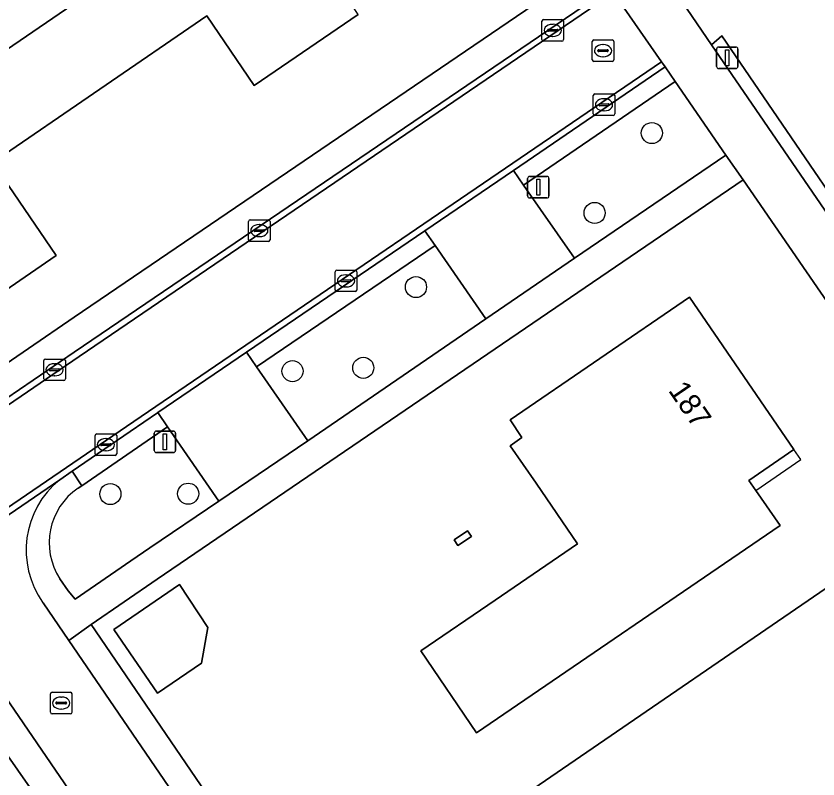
# Model space of a CAD drawing. Extents: x 155275 to 156265, y 382654 to 383635.
# Drawn here: x 155691.51 to 155728.69, y 383451.27 to 383486.64 of the extents above; entities that cross this region are included whole.
import ezdxf

# ---------------------------------------------------------------- set-up
doc = ezdxf.new("R2010")
doc.units = 0
for name, color, linetype in [('IMGEO_Boom', 7, 'Continuous'), ('IMGEO_Erf', 7, 'Continuous'), ('IMGEO_Groenvoorziening', 7, 'Continuous'), ('IMGEO_Haag', 7, 'Continuous'), ('IMGEO_Kolk', 7, 'Continuous'), ('IMGEO_Lichtmast', 7, 'Continuous'), ('IMGEO_Pand', 7, 'Continuous'), ('IMGEO_Pand_nummerreeks', 7, 'Continuous'), ('IMGEO_Pand_overbouw', 7, 'Continuous'), ('IMGEO_Parkeervlak_open', 7, 'Continuous'), ('IMGEO_Rijbaan_lokaal_open', 7, 'Continuous'), ('IMGEO_Rioolput', 7, 'Continuous'), ('IMGEO_Voetpad_open', 7, 'Continuous')]:
    doc.layers.add(name, color=color, linetype=linetype)

msp = doc.modelspace()

# ---------------------------------------------------------------- linework, layer by layer
at = {"layer": 'IMGEO_Boom'}
for centre in [(155720.99, 383481.218), (155718.335, 383477.515), (155710.055, 383474.077), (155707.611, 383470.332), (155704.33, 383470.178), (155695.889, 383464.48), (155699.492, 383464.498)]:
    msp.add_circle(centre, 0.489, dxfattribs=at)
at = {"layer": 'IMGEO_Erf'}
for points in [[(155689.952, 383469.783), (155694.204, 383472.684), (155718.29, 383489.069), (155700.65, 383514.84)], [(155707.38, 383486.712), (155702.557, 383483.422), (155700.359, 383486.653), (155690.422, 383479.861), (155693.377, 383475.537), (155688.352, 383472.093), (155683.164, 383479.665), (155687.692, 383482.78), (155695.373, 383488.031)]]:
    msp.add_lwpolyline(points, dxfattribs=at)
for points in [[(155734.512, 383465.559), (155725.215, 383479.049), (155698.054, 383460.537), (155694.998, 383458.429), (155719.873, 383421.949), (155720.07, 383422.058), (155723.062, 383417.667), (155735.929, 383398.789), (155735.874, 383398.763), (155746.045, 383383.83), (155750.929, 383387.164), (155776.093, 383404.417), (155774.449, 383406.803)], [(155712.867, 383453.41), (155710.28, 383457.206), (155713.724, 383459.565), (155717.539, 383462.177), (155715.621, 383464.979), (155714.427, 383466.723), (155714.968, 383467.095), (155714.413, 383467.914), (155722.736, 383473.61), (155727.576, 383466.544), (155725.489, 383465.114), (155725.811, 383464.647), (155726.93, 383463.025)], [(155711.824, 383462.355), (155712.45, 383462.77), (155712.622, 383462.512), (155711.996, 383462.096)], [(155717.664, 383447.195), (155717.921, 383446.826), (155717.566, 383446.593), (155710.254, 383441.58), (155707.639, 383445.383), (155714.926, 383450.427), (155730.979, 383461.428), (155735.677, 383454.594), (155724.14, 383446.672), (155721.829, 383450.056)], [(155699.086, 383460.279), (155700.405, 383458.293), (155700.109, 383456.632), (155698.071, 383455.241), (155696.048, 383458.205)], [(155689.573, 383454.56), (155686.888, 383452.74), (155667.515, 383439.536), (155668.209, 383438.49), (155691.786, 383403.993), (155718.509, 383364.995), (155740.511, 383380.044), (155700.458, 383438.718), (155700.636, 383438.742)]]:
    msp.add_lwpolyline(points, close=True, dxfattribs=at)
at = {"layer": 'IMGEO_Groenvoorziening'}
for points in [[(155720.532, 383490.035), (155723.759, 383485.312), (155724.227, 383485.725), (155777.645, 383407.499), (155785.035, 383418.096), (155785.37, 383418.576), (155786.992, 383420.901), (155789.946, 383428.782), (155786.989, 383433.092)], [(155693.549, 383460.553), (155693.935, 383459.991), (155694.252, 383459.599), (155696.833, 383461.38), (155697.716, 383461.989), (155700.919, 383464.146), (155698.538, 383467.603)], [(155698.538, 383467.603), (155694.561, 383464.865), (155694.394, 383464.75)]]:
    msp.add_lwpolyline(points, dxfattribs=at)
for points in [[(155724.227, 383485.725), (155723.759, 383485.312), (155746.216, 383452.521), (155760.092, 383432.137), (155777.308, 383407.016), (155777.645, 383407.499)], [(155722.073, 383483.608), (155715.031, 383478.804), (155717.396, 383475.423), (155724.422, 383480.2)], [(155705.034, 383466.948), (155713.291, 383472.603), (155710.944, 383476.009), (155702.66, 383470.375)]]:
    msp.add_lwpolyline(points, close=True, dxfattribs=at)
msp.add_arc((155696.094, 383462.224), 3.045, 123.9409, 213.2923, dxfattribs=at)
at = {"layer": 'IMGEO_Haag'}
msp.add_lwpolyline([(155724.227, 383485.725), (155723.759, 383485.312), (155746.216, 383452.521), (155760.092, 383432.137), (155777.308, 383407.016), (155777.645, 383407.499)], close=True, dxfattribs=at)
at = {"layer": 'IMGEO_Kolk'}
for p, q in [((155715.97, 383486.48), (155716.822, 383486.48)), ((155715.895, 383485.554), (155715.895, 383486.406)), ((155716.383, 383486.26), (155716.408, 383486.26)), ((155716.896, 383486.406), (155716.896, 383485.554)), ((155716.154, 383485.974), (155716.154, 383485.986)), ((155716.592, 383485.937), (155716.194, 383485.937)), ((155716.197, 383486.023), (155716.595, 383486.023)), ((155716.406, 383485.7), (155716.381, 383485.7)), ((155716.638, 383485.986), (155716.638, 383485.974)), ((155716.822, 383485.48), (155715.97, 383485.48)), ((155718.27, 383482.104), (155718.27, 383482.956)), ((155718.345, 383483.03), (155719.197, 383483.03)), ((155718.758, 383482.81), (155718.783, 383482.81)), ((155719.271, 383482.956), (155719.271, 383482.104)), ((155718.529, 383482.524), (155718.529, 383482.536)), ((155718.967, 383482.487), (155718.569, 383482.487)), ((155718.572, 383482.573), (155718.97, 383482.573)), ((155719.013, 383482.536), (155719.013, 383482.524)), ((155719.197, 383482.03), (155718.345, 383482.03)), ((155718.781, 383482.25), (155718.756, 383482.25)), ((155702.367, 383477.196), (155703.219, 383477.196)), ((155702.292, 383476.27), (155702.292, 383477.122)), ((155702.78, 383476.976), (155702.805, 383476.976)), ((155703.293, 383477.122), (155703.293, 383476.27)), ((155702.551, 383476.69), (155702.551, 383476.702)), ((155702.989, 383476.653), (155702.591, 383476.653)), ((155702.594, 383476.739), (155702.992, 383476.739)), ((155702.803, 383476.416), (155702.778, 383476.416)), ((155703.035, 383476.702), (155703.035, 383476.69)), ((155703.219, 383476.196), (155702.367, 383476.196)), ((155706.31, 383473.939), (155706.31, 383474.791)), ((155706.385, 383474.865), (155707.237, 383474.865)), ((155706.798, 383474.645), (155706.823, 383474.645)), ((155707.311, 383474.791), (155707.311, 383473.939)), ((155706.569, 383474.359), (155706.569, 383474.371)), ((155707.007, 383474.322), (155706.609, 383474.322)), ((155706.612, 383474.408), (155707.01, 383474.408)), ((155707.053, 383474.371), (155707.053, 383474.359)), ((155707.237, 383473.865), (155706.385, 383473.865)), ((155706.821, 383474.085), (155706.796, 383474.085)), ((155692.799, 383469.815), (155692.799, 383470.667)), ((155692.874, 383470.741), (155693.726, 383470.741)), ((155693.287, 383470.521), (155693.312, 383470.521)), ((155693.8, 383470.667), (155693.8, 383469.815)), ((155693.058, 383470.235), (155693.058, 383470.247)), ((155693.496, 383470.198), (155693.098, 383470.198)), ((155693.101, 383470.284), (155693.499, 383470.284)), ((155693.542, 383470.247), (155693.542, 383470.235)), ((155693.726, 383469.741), (155692.874, 383469.741)), ((155693.31, 383469.961), (155693.285, 383469.961)), ((155695.181, 383466.345), (155695.181, 383467.197)), ((155695.256, 383467.271), (155696.108, 383467.271)), ((155696.182, 383467.197), (155696.182, 383466.345)), ((155695.44, 383466.765), (155695.44, 383466.777)), ((155695.878, 383466.728), (155695.48, 383466.728)), ((155695.483, 383466.814), (155695.881, 383466.814)), ((155695.669, 383467.051), (155695.694, 383467.051)), ((155695.924, 383466.777), (155695.924, 383466.765)), ((155695.692, 383466.491), (155695.667, 383466.491)), ((155696.108, 383466.271), (155695.256, 383466.271)), ((155693.107, 383454.364), (155693.107, 383455.216)), ((155693.182, 383455.29), (155694.034, 383455.29)), ((155694.108, 383455.216), (155694.108, 383454.364)), ((155693.409, 383454.833), (155693.807, 383454.833)), ((155693.595, 383455.07), (155693.62, 383455.07)), ((155693.366, 383454.784), (155693.366, 383454.796)), ((155693.804, 383454.747), (155693.406, 383454.747)), ((155693.618, 383454.51), (155693.593, 383454.51)), ((155693.85, 383454.796), (155693.85, 383454.784)), ((155694.034, 383454.29), (155693.182, 383454.29))]:
    msp.add_line(p, q, dxfattribs=at)
for points in [[(155715.97, 383486.48), (155716.822, 383486.48)], [(155715.895, 383485.554), (155715.895, 383486.406)], [(155716.896, 383486.406), (155716.896, 383485.554)], [(155716.822, 383485.48), (155715.97, 383485.48)], [(155718.27, 383482.104), (155718.27, 383482.956)], [(155718.345, 383483.03), (155719.197, 383483.03)], [(155719.271, 383482.956), (155719.271, 383482.104)], [(155719.197, 383482.03), (155718.345, 383482.03)], [(155702.367, 383477.196), (155703.219, 383477.196)], [(155702.292, 383476.27), (155702.292, 383477.122)], [(155703.293, 383477.122), (155703.293, 383476.27)], [(155703.219, 383476.196), (155702.367, 383476.196)], [(155706.31, 383473.939), (155706.31, 383474.791)], [(155706.385, 383474.865), (155707.237, 383474.865)], [(155707.311, 383474.791), (155707.311, 383473.939)], [(155707.237, 383473.865), (155706.385, 383473.865)], [(155692.799, 383469.815), (155692.799, 383470.667)], [(155692.874, 383470.741), (155693.726, 383470.741)], [(155693.8, 383470.667), (155693.8, 383469.815)], [(155693.726, 383469.741), (155692.874, 383469.741)], [(155695.181, 383466.345), (155695.181, 383467.197)], [(155695.256, 383467.271), (155696.108, 383467.271)], [(155696.182, 383467.197), (155696.182, 383466.345)], [(155696.108, 383466.271), (155695.256, 383466.271)], [(155693.107, 383454.364), (155693.107, 383455.216)], [(155693.182, 383455.29), (155694.034, 383455.29)], [(155694.108, 383455.216), (155694.108, 383454.364)], [(155694.034, 383454.29), (155693.182, 383454.29)]]:
    msp.add_lwpolyline(points, dxfattribs=at)
for centre, radius, start, end in [((155715.972, 383486.404), 0.0765, 91.552, 178.448), ((155715.972, 383486.404), 0.0765, 91.552, 178.448), ((155716.82, 383486.404), 0.0765, 1.552, 88.448), ((155716.82, 383486.404), 0.0765, 1.552, 88.448), ((155716.194, 383485.983), 0.0403, 85.8775, 175.7526), ((155716.191, 383485.973), 0.0366, 178.938, 274.7102), ((155716.595, 383485.98), 0.043, 264.8664, 352.4533), ((155716.599, 383485.985), 0.0386, 1.7309, 96.639), ((155715.972, 383485.556), 0.0765, 181.552, 268.448), ((155715.972, 383485.556), 0.0765, 181.552, 268.448), ((155716.82, 383485.556), 0.0765, 271.552, 358.448), ((155716.82, 383485.556), 0.0765, 271.552, 358.448), ((155718.347, 383482.954), 0.0765, 91.552, 178.448), ((155718.347, 383482.954), 0.0765, 91.552, 178.448), ((155719.195, 383482.954), 0.0765, 1.552, 88.448), ((155719.195, 383482.954), 0.0765, 1.552, 88.448), ((155718.569, 383482.533), 0.0403, 85.8775, 175.7526), ((155718.566, 383482.523), 0.0366, 178.938, 274.7102), ((155718.97, 383482.53), 0.043, 264.8664, 352.4533), ((155718.974, 383482.535), 0.0386, 1.7309, 96.639), ((155718.347, 383482.106), 0.0765, 181.552, 268.448), ((155718.347, 383482.106), 0.0765, 181.552, 268.448), ((155719.195, 383482.106), 0.0765, 271.552, 358.448), ((155719.195, 383482.106), 0.0765, 271.552, 358.448), ((155702.369, 383477.12), 0.0765, 91.552, 178.448), ((155702.369, 383477.12), 0.0765, 91.552, 178.448), ((155703.217, 383477.12), 0.0765, 1.552, 88.448), ((155703.217, 383477.12), 0.0765, 1.552, 88.448), ((155702.591, 383476.699), 0.0403, 85.8775, 175.7526), ((155702.588, 383476.689), 0.0366, 178.938, 274.7102), ((155702.992, 383476.696), 0.043, 264.8664, 352.4533), ((155702.996, 383476.701), 0.0386, 1.7309, 96.639), ((155702.369, 383476.272), 0.0765, 181.552, 268.448), ((155702.369, 383476.272), 0.0765, 181.552, 268.448), ((155703.217, 383476.272), 0.0765, 271.552, 358.448), ((155703.217, 383476.272), 0.0765, 271.552, 358.448), ((155706.387, 383474.789), 0.0765, 91.552, 178.448), ((155706.387, 383474.789), 0.0765, 91.552, 178.448), ((155707.235, 383474.789), 0.0765, 1.552, 88.448), ((155707.235, 383474.789), 0.0765, 1.552, 88.448), ((155706.609, 383474.368), 0.0403, 85.8775, 175.7526), ((155706.606, 383474.358), 0.0366, 178.938, 274.7102), ((155707.01, 383474.365), 0.043, 264.8664, 352.4533), ((155707.014, 383474.37), 0.0386, 1.7309, 96.639), ((155706.387, 383473.941), 0.0765, 181.552, 268.448), ((155706.387, 383473.941), 0.0765, 181.552, 268.448), ((155707.235, 383473.941), 0.0765, 271.552, 358.448), ((155707.235, 383473.941), 0.0765, 271.552, 358.448), ((155692.876, 383470.665), 0.0765, 91.552, 178.448), ((155692.876, 383470.665), 0.0765, 91.552, 178.448), ((155693.724, 383470.665), 0.0765, 1.552, 88.448), ((155693.724, 383470.665), 0.0765, 1.552, 88.448), ((155693.098, 383470.244), 0.0403, 85.8775, 175.7526), ((155693.095, 383470.234), 0.0366, 178.938, 274.7102), ((155693.499, 383470.241), 0.043, 264.8664, 352.4533), ((155693.503, 383470.246), 0.0386, 1.7309, 96.639), ((155692.876, 383469.817), 0.0765, 181.552, 268.448), ((155692.876, 383469.817), 0.0765, 181.552, 268.448), ((155693.724, 383469.817), 0.0765, 271.552, 358.448), ((155693.724, 383469.817), 0.0765, 271.552, 358.448), ((155695.258, 383467.195), 0.0765, 91.552, 178.448), ((155695.258, 383467.195), 0.0765, 91.552, 178.448), ((155696.106, 383467.195), 0.0765, 1.552, 88.448), ((155696.106, 383467.195), 0.0765, 1.552, 88.448), ((155695.48, 383466.774), 0.0403, 85.8775, 175.7526), ((155695.477, 383466.764), 0.0366, 178.938, 274.7102), ((155695.881, 383466.771), 0.043, 264.8664, 352.4533), ((155695.885, 383466.776), 0.0386, 1.7309, 96.639), ((155695.258, 383466.347), 0.0765, 181.552, 268.448), ((155695.258, 383466.347), 0.0765, 181.552, 268.448), ((155696.106, 383466.347), 0.0765, 271.552, 358.448), ((155696.106, 383466.347), 0.0765, 271.552, 358.448), ((155693.184, 383455.214), 0.0765, 91.552, 178.448), ((155693.184, 383455.214), 0.0765, 91.552, 178.448), ((155694.032, 383455.214), 0.0765, 1.552, 88.448), ((155694.032, 383455.214), 0.0765, 1.552, 88.448), ((155693.406, 383454.793), 0.0403, 85.8775, 175.7526), ((155693.811, 383454.795), 0.0386, 1.7309, 96.639), ((155693.403, 383454.783), 0.0366, 178.938, 274.7102), ((155693.807, 383454.79), 0.043, 264.8664, 352.4533), ((155693.184, 383454.366), 0.0765, 181.552, 268.448), ((155693.184, 383454.366), 0.0765, 181.552, 268.448), ((155694.032, 383454.366), 0.0765, 271.552, 358.448), ((155694.032, 383454.366), 0.0765, 271.552, 358.448)]:
    msp.add_arc(centre, radius, start, end, dxfattribs=at)
for centre, major_axis, ratio, start_param, end_param in [((155716.382, 383485.98), (-0.387, 0.002), 0.722429, 4.712389, 7.853982), ((155716.407, 383485.98), (-0.39, 0.002), 0.717154, 1.570796, 4.712389), ((155718.757, 383482.53), (-0.387, 0.002), 0.722429, 4.712389, 7.853982), ((155718.782, 383482.53), (-0.39, 0.002), 0.717154, 1.570796, 4.712389), ((155702.779, 383476.696), (-0.387, 0.002), 0.722429, 4.712389, 7.853982), ((155702.804, 383476.696), (-0.39, 0.002), 0.717154, 1.570796, 4.712389), ((155706.797, 383474.365), (-0.387, 0.002), 0.722429, 4.712389, 7.853982), ((155706.822, 383474.365), (-0.39, 0.002), 0.717154, 1.570796, 4.712389), ((155693.286, 383470.241), (-0.387, 0.002), 0.722429, 4.712389, 7.853982), ((155693.311, 383470.241), (-0.39, 0.002), 0.717154, 1.570796, 4.712389), ((155695.668, 383466.771), (-0.387, 0.002), 0.722429, 4.712389, 7.853982), ((155695.693, 383466.771), (-0.39, 0.002), 0.717154, 1.570796, 4.712389), ((155693.594, 383454.79), (-0.387, 0.002), 0.722429, 4.712389, 7.853982), ((155693.619, 383454.79), (-0.39, 0.002), 0.717154, 1.570796, 4.712389)]:
    msp.add_ellipse(centre, major_axis=major_axis, ratio=ratio, start_param=start_param, end_param=end_param, dxfattribs=at)
at = {"layer": 'IMGEO_Lichtmast'}
for p, q in [((155723.987, 383484.308), (155723.987, 383485.108)), ((155723.987, 383485.108), (155723.987, 383484.308)), ((155724.087, 383485.208), (155724.877, 383485.208)), ((155724.877, 383485.208), (155724.087, 383485.208)), ((155724.977, 383485.108), (155724.977, 383484.308)), ((155724.977, 383484.308), (155724.977, 383485.108)), ((155724.877, 383484.208), (155724.087, 383484.208)), ((155724.087, 383484.208), (155724.877, 383484.208)), ((155715.23, 383478.308), (155715.23, 383479.108)), ((155715.23, 383479.108), (155715.23, 383478.308)), ((155715.33, 383479.208), (155716.12, 383479.208)), ((155716.12, 383479.208), (155715.33, 383479.208)), ((155716.22, 383479.108), (155716.22, 383478.308)), ((155716.22, 383478.308), (155716.22, 383479.108)), ((155716.12, 383478.208), (155715.33, 383478.208)), ((155715.33, 383478.208), (155716.12, 383478.208)), ((155697.922, 383466.502), (155697.922, 383467.302)), ((155697.922, 383467.302), (155697.922, 383466.502)), ((155698.022, 383467.402), (155698.812, 383467.402)), ((155698.812, 383467.402), (155698.022, 383467.402)), ((155698.912, 383467.302), (155698.912, 383466.502)), ((155698.912, 383466.502), (155698.912, 383467.302)), ((155698.812, 383466.402), (155698.022, 383466.402)), ((155698.022, 383466.402), (155698.812, 383466.402))]:
    msp.add_line(p, q, dxfattribs=at)
for points in [[(155724.407, 383485.083), (155724.557, 383485.083), (155724.557, 383484.333), (155724.407, 383484.333), (155724.407, 383485.083)], [(155715.65, 383479.083), (155715.8, 383479.083), (155715.8, 383478.333), (155715.65, 383478.333), (155715.65, 383479.083)], [(155698.342, 383467.277), (155698.492, 383467.277), (155698.492, 383466.527), (155698.342, 383466.527), (155698.342, 383467.277)]]:
    msp.add_lwpolyline(points, dxfattribs=at)
for centre, start, end in [((155724.087, 383485.108), 90, 180), ((155724.087, 383485.108), 90, 180), ((155724.877, 383485.108), 0, 90), ((155724.877, 383485.108), 360, 90), ((155724.087, 383484.308), 180, 270), ((155724.087, 383484.308), 180, 270), ((155724.877, 383484.308), 270, 0), ((155724.877, 383484.308), 270, 0), ((155715.33, 383479.108), 90, 180), ((155715.33, 383479.108), 90, 180), ((155716.12, 383479.108), 0, 90), ((155716.12, 383479.108), 360, 90), ((155715.33, 383478.308), 180, 270), ((155715.33, 383478.308), 180, 270), ((155716.12, 383478.308), 270, 0), ((155716.12, 383478.308), 270, 0), ((155698.022, 383467.302), 90, 180), ((155698.022, 383467.302), 90, 180), ((155698.812, 383467.302), 0, 90), ((155698.812, 383467.302), 360, 90), ((155698.022, 383466.502), 180, 270), ((155698.022, 383466.502), 180, 270), ((155698.812, 383466.502), 270, 0), ((155698.812, 383466.502), 270, 0)]:
    msp.add_arc(centre, 0.1, start, end, dxfattribs=at)
at = {"layer": 'IMGEO_Pand'}
for points in [[(155710.434, 383491.556), (155707.613, 383495.699), (155707.477, 383495.899), (155695.572, 383487.74), (155695.373, 383488.031), (155687.692, 383482.78), (155683.164, 383479.665), (155688.352, 383472.093), (155693.377, 383475.537), (155690.422, 383479.861), (155700.359, 383486.653), (155702.557, 383483.422), (155707.38, 383486.712), (155706.116, 383488.6)], [(155727.576, 383466.544), (155722.736, 383473.61), (155714.413, 383467.914), (155714.968, 383467.095), (155714.427, 383466.723), (155715.621, 383464.979), (155717.539, 383462.177), (155713.724, 383459.565), (155710.28, 383457.206), (155712.867, 383453.41), (155726.93, 383463.025), (155725.811, 383464.647), (155725.489, 383465.114)], [(155711.824, 383462.355), (155711.996, 383462.096), (155712.622, 383462.512), (155712.45, 383462.77)], [(155717.566, 383446.593), (155717.921, 383446.826), (155717.664, 383447.195), (155721.829, 383450.056), (155724.14, 383446.672), (155735.677, 383454.594), (155730.979, 383461.428), (155714.926, 383450.427), (155707.639, 383445.383), (155710.254, 383441.58)], [(155699.086, 383460.279), (155696.048, 383458.205), (155698.071, 383455.241), (155700.109, 383456.632), (155700.405, 383458.293)]]:
    msp.add_lwpolyline(points, close=True, dxfattribs=at)
at = {"layer": 'IMGEO_Pand_overbouw'}
msp.add_lwpolyline([(155727.576, 383466.544), (155725.489, 383465.114), (155725.811, 383464.647), (155727.895, 383466.081)], close=True, dxfattribs=at)
at = {"layer": 'IMGEO_Parkeervlak_open'}
for points in [[(155715.031, 383478.804), (155714.572, 383479.488), (155710.462, 383476.687), (155710.944, 383476.009), (155713.291, 383472.603), (155717.396, 383475.423)], [(155702.66, 383470.375), (155702.196, 383471.054), (155698.088, 383468.255), (155698.538, 383467.603), (155700.919, 383464.146), (155705.034, 383466.948)]]:
    msp.add_lwpolyline(points, close=True, dxfattribs=at)
at = {"layer": 'IMGEO_Rijbaan_lokaal_open'}
for points in [[(155719.204, 383487.735), (155719.05, 383487.959), (155694.212, 383471.066), (155691.045, 383468.901), (155681.838, 383462.606), (155655.747, 383444.77), (155630.619, 383427.541), (155621.24, 383421.11), (155600.732, 383407.049), (155600.872, 383406.808), (155655.916, 383444.522), (155694.436, 383470.854)], [(155658.271, 383441.395), (155696.637, 383467.612), (155721.44, 383484.524), (155719.204, 383487.735), (155694.436, 383470.854), (155655.916, 383444.522), (155600.872, 383406.808), (155603.126, 383403.562)]]:
    msp.add_lwpolyline(points, close=True, dxfattribs=at)
for points in [[(155672.897, 383451.033), (155681.099, 383456.641), (155684.176, 383458.745), (155693.537, 383465.146), (155694.112, 383465.539), (155696.8, 383467.377), (155698.079, 383468.249), (155698.088, 383468.255), (155702.196, 383471.054), (155710.462, 383476.687), (155714.572, 383479.488), (155721.608, 383484.282), (155721.44, 383484.524), (155696.637, 383467.612), (155658.271, 383441.395)], [(155693.537, 383465.146), (155684.176, 383458.745)], [(155693.961, 383457.69), (155692.764, 383459.442)], [(155746.215, 383381.223), (155744.93, 383383.103), (155693.961, 383457.69)], [(155689.529, 383457.271), (155690.812, 383455.393), (155741.737, 383380.843), (155743, 383378.994)]]:
    msp.add_lwpolyline(points, dxfattribs=at)
msp.add_arc((155696.187, 383461.882), 4.204, 129.0781, 215.4866, dxfattribs=at)
at = {"layer": 'IMGEO_Rioolput'}
for p, q in [((155718.225, 383484.612), (155718.225, 383485.464)), ((155718.3, 383485.538), (155719.152, 383485.538)), ((155718.713, 383485.318), (155718.738, 383485.318)), ((155719.226, 383485.464), (155719.226, 383484.612)), ((155718.484, 383485.032), (155718.484, 383485.044)), ((155718.922, 383484.995), (155718.524, 383484.995)), ((155718.527, 383485.081), (155718.925, 383485.081)), ((155718.968, 383485.044), (155718.968, 383485.032)), ((155718.736, 383484.758), (155718.711, 383484.758)), ((155719.152, 383484.538), (155718.3, 383484.538))]:
    msp.add_line(p, q, dxfattribs=at)
for points in [[(155718.225, 383484.612), (155718.225, 383485.464)], [(155718.3, 383485.538), (155719.152, 383485.538)], [(155719.226, 383485.464), (155719.226, 383484.612)], [(155719.152, 383484.538), (155718.3, 383484.538)]]:
    msp.add_lwpolyline(points, dxfattribs=at)
for centre, radius, start, end in [((155718.302, 383485.462), 0.0765, 91.552, 178.448), ((155718.302, 383485.462), 0.0765, 91.552, 178.448), ((155719.15, 383485.462), 0.0765, 1.552, 88.448), ((155719.15, 383485.462), 0.0765, 1.552, 88.448), ((155718.524, 383485.041), 0.0403, 85.8775, 175.7526), ((155718.521, 383485.031), 0.0366, 178.938, 274.7102), ((155718.925, 383485.038), 0.043, 264.8664, 352.4533), ((155718.929, 383485.043), 0.0386, 1.7309, 96.639), ((155718.302, 383484.614), 0.0765, 181.552, 268.448), ((155718.302, 383484.614), 0.0765, 181.552, 268.448), ((155719.15, 383484.614), 0.0765, 271.552, 358.448), ((155719.15, 383484.614), 0.0765, 271.552, 358.448)]:
    msp.add_arc(centre, radius, start, end, dxfattribs=at)
for centre, major_axis, ratio, start_param, end_param in [((155718.712, 383485.038), (-0.387, 0.002), 0.722429, 4.712389, 7.853982), ((155718.737, 383485.038), (-0.39, 0.002), 0.717154, 1.570796, 4.712389)]:
    msp.add_ellipse(centre, major_axis=major_axis, ratio=ratio, start_param=start_param, end_param=end_param, dxfattribs=at)
at = {"layer": 'IMGEO_Voetpad_open'}
for points in [[(155746.216, 383452.521), (155723.759, 383485.312), (155720.532, 383490.035), (155719.771, 383491.148), (155719.708, 383491.241), (155701.514, 383517.87), (155701.108, 383518.439), (155696.77, 383524.522), (155694.942, 383523.334), (155699.6, 383516.374), (155700.65, 383514.84), (155718.29, 383489.069), (155719.05, 383487.959), (155719.204, 383487.735), (155721.44, 383484.524), (155721.608, 383484.282), (155722.073, 383483.608), (155724.422, 383480.2), (155725.215, 383479.049), (155734.512, 383465.559)], [(155725.215, 383479.049), (155724.422, 383480.2), (155717.396, 383475.423), (155713.291, 383472.603), (155705.034, 383466.948), (155700.919, 383464.146), (155697.716, 383461.989), (155696.833, 383461.38), (155694.252, 383459.599), (155693.935, 383459.991), (155693.549, 383460.553)], [(155692.764, 383459.442), (155693.961, 383457.69), (155694.998, 383458.429), (155698.054, 383460.537), (155725.215, 383479.049)], [(155694.394, 383464.75), (155694.561, 383464.865), (155694.112, 383465.539), (155693.537, 383465.146)]]:
    msp.add_lwpolyline(points, dxfattribs=at)
for points in [[(155719.05, 383487.959), (155718.29, 383489.069), (155694.204, 383472.684), (155689.952, 383469.783), (155691.045, 383468.901), (155694.212, 383471.066)], [(155721.608, 383484.282), (155714.572, 383479.488), (155715.031, 383478.804), (155722.073, 383483.608)], [(155702.196, 383471.054), (155702.66, 383470.375), (155710.944, 383476.009), (155710.462, 383476.687)], [(155698.538, 383467.603), (155698.088, 383468.255), (155698.079, 383468.249), (155696.8, 383467.377), (155694.112, 383465.539), (155694.561, 383464.865)], [(155720.07, 383422.058), (155719.873, 383421.949), (155694.998, 383458.429), (155693.961, 383457.69), (155744.93, 383383.103), (155746.045, 383383.83), (155735.874, 383398.763), (155735.929, 383398.789), (155723.062, 383417.667)], [(155690.812, 383455.393), (155689.573, 383454.56), (155700.636, 383438.742), (155700.458, 383438.718), (155740.511, 383380.044), (155741.737, 383380.843)]]:
    msp.add_lwpolyline(points, close=True, dxfattribs=at)
for centre, radius, start, end in [((155696.187, 383461.882), 4.204, 129.0781, 215.4866), ((155696.094, 383462.224), 3.045, 123.9409, 213.2923)]:
    msp.add_arc(centre, radius, start, end, dxfattribs=at)

# ---------------------------------------------------------------- texts
at = {"layer": 'IMGEO_Pand_nummerreeks'}
msp.add_text('187', height=1, rotation=304.4092, dxfattribs=at).set_placement((155721.724, 383469.283))

doc.saveas('drawing.dxf')
